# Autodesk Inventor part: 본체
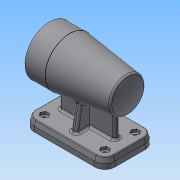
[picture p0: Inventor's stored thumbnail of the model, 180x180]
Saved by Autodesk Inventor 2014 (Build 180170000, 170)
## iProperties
Created: 2017-01
Part Number: 본체
Material: Generic
Document SubType Name: Modeling
Designer: 702
Density: 1 g/cm^3
Appearance: Default
Author: 702
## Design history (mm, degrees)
sketch "스케치1"
  geometry: L1 (-42, 35)-(42, 35); L2 (56, 21)-(56, -21); L3 (42, -35)-(-42, -35); L4 (-56, -21)-(-56, 21); A1 r 14 centre (-42, -21) between (-56, -21) and (-42, -35); A2 r 14 centre (-42, 21) between (-42, 35) and (-56, 21); A3 r 14 centre (42, 21) between (56, 21) and (42, 35); A4 r 14 centre (42, -21) between (42, -35) and (56, -21); 6 further points
  constraints: 8 end point, 8 point on circle, 8 tangent, 6 point on line, 4 centre point, 3 equal radius, 2 midpoint, 2 parallel, 1 horizontal, 1 horizontal alignment, 1 perpendicular, 1 vertical alignment
extrude "돌출3" join sketch "스케치1" distance "d56" = 7; taper "d57" = 0 deg
sketch "스케치6"
  geometry: L1 (-56, 21)-(-56, -21) reference; L2 (-42, -35)-(42, -35) reference; L3 (56, -21)-(56, 21) reference; L4 (42, 35)-(-42, 35) reference; A1 r 14 centre (-42, -21) between (-56, -21) and (-42, -35) reference; A2 r 14 centre (42, -21) between (42, -35) and (56, -21) reference; A3 r 14 centre (42, 21) between (56, 21) and (42, 35) reference; A4 r 14 centre (-42, 21) between (-42, 35) and (-56, 21) reference; 1 further point
extrude "돌출4" join sketch "스케치6" distance "d58" = 7; taper "d59" = -15 deg
sketch "스케치7"
  geometry: L1 (56, 108)-(28, 108); L2 (28, 108)-(-50.331, 98.382); L3 (55, 95)-(41, 95); L4 (38, 98)-(-10, 98); L5 (-13, 95)-(-24.7, 95); L6 (-25, 91.5)-(-42.7, 91.5); L7 (-43, 90)-(-46.7, 90); L8 (-47, 84.5)-(-49, 84.5); L9 (0, 74)-(72.161, 74); L10 (-50, 83.5)-(-50, 74); L11 (-47, 89.7)-(-47, 84.5); L12 (-43, 91.2)-(-43, 90); L13 (-25, 94.7)-(-25, 91.5); L14 (-13, 95)-(-13, 95); L15 (41, 95)-(41, 95); L16 (56, 108)-(56, 96); L17 (-50, 74)-(-56, 74); L18 (-50, 83.5)-(-49, 84.5); L19 (55, 95)-(56, 96); A1 r 80 centre (24, 74) between (-52.847, 96.238) and (-56, 74); A2 r 3 centre (-10, 95) between (-10, 98) and (-13, 95); A3 r 3 centre (38, 95) between (41, 95) and (38, 98); A4 r 0.3 centre (-46.7, 89.7) between (-46.7, 90) and (-47, 89.7); A5 r 0.3 centre (-42.7, 91.2) between (-42.7, 91.5) and (-43, 91.2); A6 r 0.3 centre (-24.7, 94.7) between (-24.7, 95) and (-25, 94.7); A7 r 3 centre (-49.965, 95.405) between (-50.331, 98.382) and (-52.847, 96.238); 4 further points
  constraints: 38 end point, 15 point on circle, 12 tangent, 10 parallel, 7 centre point, 5 point on line, 2 equal radius, 2 perpendicular
revolve "회전2" sketch "스케치7" stored, may be unused: angle "d94" = 90 deg
sketch "스케치8"
  geometry: L1 (38, -4)-(-38, -4); L2 (38, -4)-(38, 4); L3 (38, 4)-(-38, 4); L4 (-38, -4)-(-38, 4); L5 (44.887, -16)-(47.774, -21); L6 (47.774, -21)-(44.887, -26); L7 (44.887, -26)-(39.113, -26); L8 (39.113, -26)-(36.226, -21); L9 (36.226, -21)-(39.113, -16); L10 (39.113, -16)-(44.887, -16); L11 (44.887, 26)-(47.774, 21); L12 (47.774, 21)-(44.887, 16); L13 (44.887, 16)-(39.113, 16); L14 (39.113, 16)-(36.226, 21); L15 (36.226, 21)-(39.113, 26); L16 (39.113, 26)-(44.887, 26); L17 (-39.113, 26)-(-36.226, 21); L18 (-36.226, 21)-(-39.113, 16); L19 (-39.113, 16)-(-44.887, 16); L20 (-44.887, 16)-(-47.774, 21); L21 (-47.774, 21)-(-44.887, 26); L22 (-44.887, 26)-(-39.113, 26); L23 (-39.113, -16)-(-36.226, -21); L24 (-36.226, -21)-(-39.113, -26); L25 (-39.113, -26)-(-44.887, -26); L26 (-44.887, -26)-(-47.774, -21); L27 (-47.774, -21)-(-44.887, -16); L28 (-44.887, -16)-(-39.113, -16); 13 further points
  constraints: 56 end point, 4 coincident, 4 midpoint, 3 perpendicular, 52 other
extrude "돌출5" join sketch "스케치8" stored distance "d103" = 7; taper "d104" = 0 deg
sketch "스케치9"
  geometry: L1 (23, 14)-(16.054, 53.392); 1 further point
  constraints: 2 end point
feature "리브1" sketch "스케치9" dims "d108" = 1, "d109" = 8, "d110" = 0, "d111" = 0, "d112" = 1, "d113" = 1
sketch "스케치10"
  geometry: 5 further points
hole "구멍1" sketch "스케치10" at (26, 0), (0, 26), (-26, 0), (0, -26) diameter "d115" = 3.242; stored, may be unused: countersink angle "d119" = 90 deg, drill point angle "d121" = 118 deg; dims "d116" = 8, "d117" = 4, "d118" = 2, "d120" = 11
extrude "돌출6" cut sketch "스케치8" distance "d122" = 4; taper "d123" = 0 deg
hole "구멍2" sketch "스케치8" diameter "d124" = 5; stored, may be unused: countersink angle "d128" = 90 deg, drill point angle "d130" = 118 deg; dims "d125" = 8, "d126" = 4, "d127" = 2, "d129" = 11
fillet "모깎기1" dims "d131" = 1, "d132" = 3
fillet "모깎기2" dims "d133" = 3
sketch "스케치11"
  geometry: 2 further points
  constraints: 1 other
feature "엠보싱2" sketch "스케치11" dims "d135" = 0.5, "d136" = 0
node "솔리드1"
mirror "대칭1"
